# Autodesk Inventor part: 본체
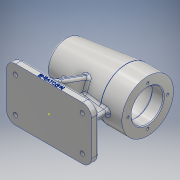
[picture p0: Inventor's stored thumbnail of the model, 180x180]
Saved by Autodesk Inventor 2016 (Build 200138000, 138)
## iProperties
Created: 2018-09
Part Number: 본체
Material: 알루미늄 6061
Document SubType Name: Modeling
Designer: CAMTIC
Density: 2.7 g/cm^3
Appearance: 알루미늄 - 평지
Mass: 732.752 g
Surface Area: 663.622 cm^2
Volume: 271.389 cm^3
Author: CAMTIC
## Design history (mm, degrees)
sketch "스케치1"
  geometry: L1 (56, -35)-(-56, -35); L2 (-56, -35)-(-56, 35); L3 (-56, 35)-(56, 35); L4 (56, 35)-(56, -35); L5 (0, -49)-(0, 49) reference; L6 (-78.4, 0)-(78.4, 0) reference; 1 further point
  constraints: 8 end point, 2 parallel, 1 horizontal, 1 perpendicular, 2 other
  dimensions: "d0" = 112 distance of L2.end L3.end; "d1" = 70 distance of L1.end L2.end
extrude "돌출1" new body sketch "스케치1" distance "d2" = 10; taper "d3" = 0 deg
sketch "스케치3"
  geometry: L1 (-56, 0)-(-56, 10) reference; L2 (-56, 10)-(56, 10) reference; L3 (56, 10)-(56, 0) reference; L4 (56, 0)-(-56, 0) reference; L5 (-78.4, 0)-(78.4, 0) reference; L6 (0, 12)-(0, -2) reference; L7 (-89.894, 74)-(120.731, 74); L8 (56, 74)-(56, 108); L9 (56, 108)-(28, 108); L10 (-56, 115.931)-(-56, 37.674); L11 (28, 108)-(-52.27, 98.144); L12 (-56, 74)-(56, 74); A1 r 80 centre (24, 74) between (54.397, 0) and (56, 0.679); A2 r 80 centre (24, 74) between (-52.27, 98.144) and (-56, 74); 1 further point
  constraints: 12 end point, 5 point on line, 4 point on circle, 2 centre point, 2 collinear, 2 horizontal, 2 vertical, 1 tangent
  dimensions: "d4" = 74 distance between parallel lines of L7 L4; "d5" = 34 distance of L8.start L8.end; "d6" = 28 distance of L8.end L9.end; "d7" = 112 distance between parallel lines of L8 L10; "d8" = 7 deg angle of L9 L11; "d10" = 80 radius of A2
revolve "회전1" sketch "스케치3" stored, may be unused: angle "d11" = 90 deg
sketch "스케치4"
  geometry: L1 (-56, 0)-(-56, 10) reference; L2 (-56, 10)-(56, 10) reference; L3 (56, 10)-(56, 0) reference; L4 (56, 0)-(-56, 0) reference; L5 (-52.27, 98.144)-(28, 108) reference; L6 (28, 108)-(56, 108) reference; L7 (56, 108)-(56, 40) reference; L8 (56, 40)-(28, 40) reference; L9 (28, 40)-(-52.27, 49.856) reference; L10 (-38, 10)-(-25.942, 55); L11 (-25.942, 55)-(38, 55); L12 (38, 55)-(38, 10); L13 (56, 10)-(-56, 10) reference; L14 (38, 10)-(-38, 10); A1 r 80 centre (24, 74) between (-52.27, 98.144) and (-52.27, 49.856) reference; 1 further point
  constraints: 8 end point, 2 point on line, 1 collinear, 1 horizontal, 1 perpendicular
  dimensions: "d12" = 18 distance from line of L1 L10.start; "d13" = 18 distance between parallel lines of L3 L12; "d14" = 105 deg angle of L2 L10; "d15" = 45 distance of L11.end L12.end
extrude "돌출2" join sketch "스케치4" stored distance "d16" = 8; taper "d17" = 0 deg
fillet "모깎기2" dims "d51" = 12
fillet "모깎기13" dims "d75" = 3
sketch "스케치5"
  geometry: L1 (7, -35)-(0, -35) reference; L2 (0, -35)-(0, 35) reference; L3 (0, 35)-(7, 35) reference; L4 (10, 32)-(10, 4) reference; L5 (10, 4)-(43.701, 4) reference; L6 (43.701, -4)-(10, -4) reference; L7 (10, -4)-(10, -32) reference; L8 (0, 49)-(0, -49) reference; L9 (-21.6, 0)-(129.6, 0) reference; L10 (10, -35)-(10, 35) reference; L11 (10, 35)-(10, -35); L12 (60, -15.902)-(60, 15.902); L13 (60, 15.902)-(8.026, 34.819); L14 (60, -15.902)-(8.026, -34.819); L15 (8.026, 34.819)-(8.026, -34.819); A1 r 30.562 centre (74, 0) between (43.701, -4) and (43.701, 4) reference; A2 r 3 centre (7, -32) between (7, -35) and (10, -32) reference; A3 r 3 centre (7, 32) between (10, 32) and (7, 35) reference; 1 further point
  constraints: 10 end point, 2 symmetric about line, 1 parallel, 1 point on circle, 1 point on line, 1 tangent, 1 vertical
  dimensions: "d19" = 50 distance between parallel lines of L7 L12; "d76" = 20 deg angle of L13 L3
extrude "돌출3" join sketch "스케치5" stored distance "d20" = 8; taper "d21" = 0 deg
sketch "스케치6"
  geometry: L1 (56, 7)-(56, 0) reference; L2 (56, 0)-(-56, 0) reference; L3 (-56, 0)-(-56, 7) reference; L4 (-53, 10)-(-38, 10) reference; L5 (-38, 10)-(-28.115, 46.89) reference; L6 (-28.115, 46.89)-(-52.27, 49.856) reference; L7 (-52.27, 98.144)-(28, 108) reference; L8 (28, 108)-(56, 108) reference; L9 (56, 108)-(56, 40) reference; L10 (56, 40)-(38, 40) reference; L11 (38, 40)-(38, 10) reference; L12 (38, 10)-(53, 10) reference; L13 (-78.4, 0)-(78.4, 0) reference; L14 (0, 129.6)-(0, -21.6) reference; L15 (56, 40)-(56, 108) reference; L16 (56, 95)-(41, 95); L17 (41, 95)-(41, 98); L18 (41, 98)-(-13, 98); L19 (-13, 98)-(-13, 95); L20 (-13, 95)-(-25, 95); L21 (-25, 95)-(-25, 91.5); L22 (-25, 91.5)-(-43, 91.5); L23 (-43, 91.5)-(-43, 90); L24 (-43, 90)-(-47, 90); L25 (-47, 90)-(-47, 84.5); L26 (-52.27, 49.856)-(-52.27, 98.144) reference; L27 (-47, 84.5)-(-50, 84.5); L28 (-50, 84.5)-(-50, 74); L29 (56, 74)-(-128.462, 74); L30 (-50, 74)-(56, 74); L31 (56, 95)-(56, 74); A1 r 80 centre (24, 74) between (-52.27, 98.144) and (-52.27, 49.856) reference; A2 r 3 centre (53, 7) between (56, 7) and (53, 10) reference; A3 r 3 centre (-53, 7) between (-53, 10) and (-56, 7) reference; 1 further point
  constraints: 30 end point, 12 perpendicular, 2 collinear, 2 point on line, 1 midpoint, 1 parallel
  dimensions: "d22" = 21 distance between parallel lines of L29 L16; "d23" = 15 distance of L16.start L16.end; "d24" = 54 distance of L17.end L18.end; "d25" = 24 distance between parallel lines of L29 L18; "d26" = 12 distance of L19.end L20.end; "d27" = 21 distance between parallel lines of L29 L20; "d28" = 18 distance of L21.end L22.end; "d29" = 17.5 distance between parallel lines of L29 L22; "d30" = 4 distance of L23.end L24.end; "d31" = 16 distance between parallel lines of L29 L24; "d32" = 10.5 distance between parallel lines of L29 L27; "d33" = 3 distance of L25.end L27.end
revolve "회전2" sketch "스케치6" stored, may be unused: angle "d34" = 90 deg
fillet "모깎기1" dims "d38" = 3, "d39" = 0.3
chamfer "모따기1" distance "d35" = 1; stored, may be unused: second distance "d36" = 2, angle "d37" = 45 deg
sketch "스케치7" dims "d40" = 52
  geometry: L1 (0, 0)-(0, 55.004); C1 r 10.5 at (0, 0) reference; 3 further points
  constraints: 2 end point, 1 coincident, 1 point on line, 1 vertical, 1 vertical alignment, 2 other
hole "구멍1" sketch "스케치7" at (0, 26) diameter "d41" = 3.242; stored, may be unused: countersink angle "d45" = 90 deg, drill point angle "d47" = 118 deg; dims "d42" = 8, "d43" = 4, "d44" = 2, "d46" = 11
hole "구멍2" diameter "d54" = 5.5; stored, may be unused: countersink angle "d58" = 90 deg, drill point angle "d60" = 118 deg; dims "d52" = 10, "d53" = 10, "d55" = 8, "d56" = 9.5, "d57" = 5.4, "d59" = 11
fillet "모깎기12" dims "d74" = 3
fillet "모깎기14" dims "d77" = 3
fillet "모깎기15" dims "d78" = 3
sketch "스케치9"
  geometry: L1 (88, 0)-(0, 0) reference; L2 (100, 0)-(100, 7) reference; 2 further points
  constraints: 1 other
  dimensions: "d84" = 3 distance from line of L1 point (44, 3); "d85" = 56 distance from line of L2 point (44, 3)
feature "엠보싱2" sketch "스케치9" dims "d0" = 112, "d1" = 70, "d86" = 0.5, "d87" = 0
fillet "모깎기17" dims "d88" = 3
fillet "모깎기18" dims "d89" = 3
fillet "모깎기19" dims "d90" = 3
fillet "모깎기20" dims "d91" = 3
fillet "모깎기21" dims "d92" = 3
node "솔리드1"
pattern_circular "원형 패턴1" dims angle "d49" = 360 deg
mirror "대칭1"
mirror "대칭2"
node "절단 모서리 투영1"
node "절단 모서리 투영2"
node "절단 모서리 투영3"
node "절단 모서리 투영4"
